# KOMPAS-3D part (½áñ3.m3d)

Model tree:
1. Эскиз:1
2. Операция выдавливания:1
     Расстояние 1 = 20
3. Эскиз:2
4. Операция выдавливания:2
     Расстояние 1 = 400
5. Эскиз:3
6. Вырезать элемент выдавливания:1
     Расстояние 1 = 70
7. Эскиз:4
8. Вырезать элемент выдавливания:2
     Расстояние 1 = 2
9. Эскиз:5
10. Эскиз:11
11. Вырезать элемент выдавливания:7
     Расстояние 1 = 30
12. Эскиз:12
13. Вырезать элемент выдавливания:8
     Расстояние 1 = 30
